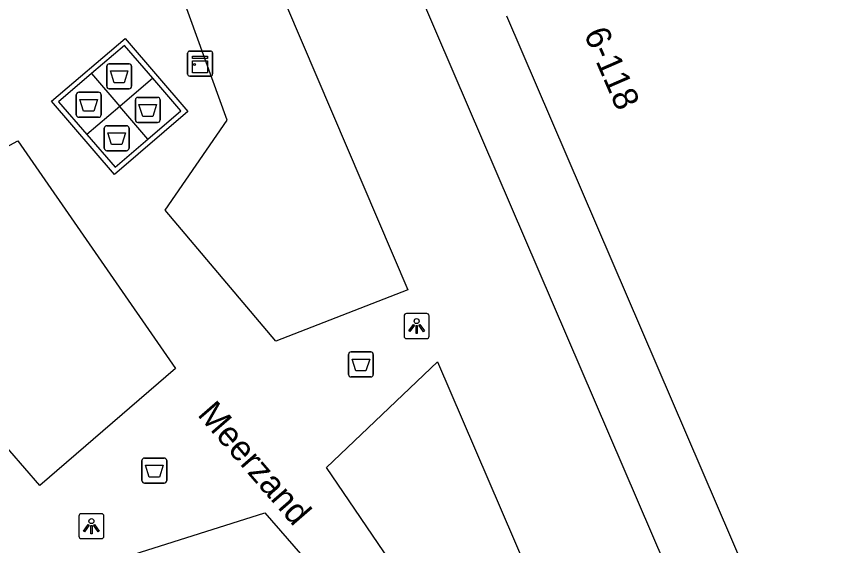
# Model space of a CAD drawing. Extents: x 155640 to 156810, y 382822 to 384046.
# Drawn here: x 156509.49 to 156542.78, y 383768.27 to 383789.39 of the extents above; entities that cross this region are included whole.
import ezdxf

# ---------------------------------------------------------------- set-up
doc = ezdxf.new("R2010")
doc.units = 0
for name, color, linetype in [('IMGEO_Afval_apart_plaats', 7, 'Continuous'), ('IMGEO_Afvalbak', 7, 'Continuous'), ('IMGEO_Kast', 7, 'Continuous'), ('IMGEO_Lichtpunt', 7, 'Continuous'), ('IMGEO_Lijnafwatering', 7, 'Continuous'), ('IMGEO_Muur', 7, 'Continuous'), ('IMGEO_Openbare_ruimte_label', 7, 'Continuous'), ('IMGEO_Pand', 7, 'Continuous'), ('IMGEO_Pand_nummerreeks', 7, 'Continuous'), ('IMGEO_Voetgangersgebied_open', 7, 'Continuous'), ('IMGEO_Voetpad_gesloten', 7, 'Continuous')]:
    doc.layers.add(name, color=color, linetype=linetype)

msp = doc.modelspace()

# ---------------------------------------------------------------- linework, layer by layer
at = {"layer": 'IMGEO_Afval_apart_plaats'}
for p, q in [((156513.093, 383786.609), (156513.093, 383787.409)), ((156513.093, 383787.409), (156513.093, 383786.609)), ((156513.193, 383787.509), (156513.983, 383787.509)), ((156513.983, 383787.509), (156513.193, 383787.509)), ((156514.083, 383787.409), (156514.083, 383786.609)), ((156514.083, 383786.609), (156514.083, 383787.409)), ((156511.874, 383785.473), (156511.874, 383786.273)), ((156511.874, 383786.273), (156511.874, 383785.473)), ((156511.974, 383786.373), (156512.764, 383786.373)), ((156512.764, 383786.373), (156511.974, 383786.373)), ((156512.864, 383786.273), (156512.864, 383785.473)), ((156512.864, 383785.473), (156512.864, 383786.273)), ((156513.983, 383786.509), (156513.193, 383786.509)), ((156513.193, 383786.509), (156513.983, 383786.509)), ((156514.235, 383785.264), (156514.235, 383786.064)), ((156514.235, 383786.064), (156514.235, 383785.264)), ((156514.335, 383786.164), (156515.125, 383786.164)), ((156515.125, 383786.164), (156514.335, 383786.164)), ((156515.225, 383786.064), (156515.225, 383785.264)), ((156515.225, 383785.264), (156515.225, 383786.064)), ((156512.764, 383785.373), (156511.974, 383785.373)), ((156511.974, 383785.373), (156512.764, 383785.373)), ((156512.993, 383784.136), (156512.993, 383784.936)), ((156512.993, 383784.936), (156512.993, 383784.136)), ((156513.093, 383785.036), (156513.883, 383785.036)), ((156513.883, 383785.036), (156513.093, 383785.036)), ((156513.983, 383784.936), (156513.983, 383784.136)), ((156513.983, 383784.136), (156513.983, 383784.936)), ((156515.125, 383785.164), (156514.335, 383785.164)), ((156514.335, 383785.164), (156515.125, 383785.164)), ((156513.883, 383784.036), (156513.093, 383784.036)), ((156513.093, 383784.036), (156513.883, 383784.036))]:
    msp.add_line(p, q, dxfattribs=at)
for points in [[(156513.236, 383787.223), (156513.94, 383787.223), (156513.791, 383786.753), (156513.385, 383786.753), (156513.236, 383787.223)], [(156512.017, 383786.087), (156512.721, 383786.087), (156512.572, 383785.617), (156512.166, 383785.617), (156512.017, 383786.087)], [(156514.378, 383785.878), (156515.082, 383785.878), (156514.933, 383785.408), (156514.527, 383785.408), (156514.378, 383785.878)], [(156513.136, 383784.75), (156513.84, 383784.75), (156513.691, 383784.28), (156513.285, 383784.28), (156513.136, 383784.75)]]:
    msp.add_lwpolyline(points, dxfattribs=at)
for centre, start, end in [((156513.193, 383787.409), 90, 180), ((156513.193, 383787.409), 90, 180), ((156513.983, 383787.409), 0, 90), ((156513.983, 383787.409), 360, 90), ((156513.193, 383786.609), 180, 270), ((156513.193, 383786.609), 180, 270), ((156513.983, 383786.609), 270, 0), ((156513.983, 383786.609), 270, 0), ((156511.974, 383786.273), 90, 180), ((156511.974, 383786.273), 90, 180), ((156512.764, 383786.273), 0, 90), ((156512.764, 383786.273), 360, 90), ((156514.335, 383786.064), 90, 180), ((156514.335, 383786.064), 90, 180), ((156515.125, 383786.064), 0, 90), ((156515.125, 383786.064), 360, 90), ((156511.974, 383785.473), 180, 270), ((156511.974, 383785.473), 180, 270), ((156512.764, 383785.473), 270, 0), ((156512.764, 383785.473), 270, 0), ((156514.335, 383785.264), 180, 270), ((156514.335, 383785.264), 180, 270), ((156515.125, 383785.264), 270, 0), ((156515.125, 383785.264), 270, 0), ((156513.093, 383784.936), 90, 180), ((156513.093, 383784.936), 90, 180), ((156513.883, 383784.936), 0, 90), ((156513.883, 383784.936), 360, 90), ((156513.093, 383784.136), 180, 270), ((156513.093, 383784.136), 180, 270), ((156513.883, 383784.136), 270, 0), ((156513.883, 383784.136), 270, 0)]:
    msp.add_arc(centre, 0.1, start, end, dxfattribs=at)
at = {"layer": 'IMGEO_Afvalbak'}
for p, q in [((156522.757, 383775.099), (156522.757, 383775.899)), ((156522.757, 383775.899), (156522.757, 383775.099)), ((156522.857, 383775.999), (156523.647, 383775.999)), ((156523.647, 383775.999), (156522.857, 383775.999)), ((156523.747, 383775.899), (156523.747, 383775.099)), ((156523.747, 383775.099), (156523.747, 383775.899)), ((156523.647, 383774.999), (156522.857, 383774.999)), ((156522.857, 383774.999), (156523.647, 383774.999)), ((156514.498, 383770.854), (156514.498, 383771.654)), ((156514.498, 383771.654), (156514.498, 383770.854)), ((156514.598, 383771.754), (156515.388, 383771.754)), ((156515.388, 383771.754), (156514.598, 383771.754)), ((156515.488, 383771.654), (156515.488, 383770.854)), ((156515.488, 383770.854), (156515.488, 383771.654)), ((156515.388, 383770.754), (156514.598, 383770.754)), ((156514.598, 383770.754), (156515.388, 383770.754))]:
    msp.add_line(p, q, dxfattribs=at)
for points in [[(156522.9, 383775.713), (156523.604, 383775.713), (156523.455, 383775.243), (156523.049, 383775.243), (156522.9, 383775.713)], [(156514.641, 383771.468), (156515.345, 383771.468), (156515.196, 383770.998), (156514.79, 383770.998), (156514.641, 383771.468)]]:
    msp.add_lwpolyline(points, dxfattribs=at)
for centre, start, end in [((156522.857, 383775.899), 90, 180), ((156522.857, 383775.899), 90, 180), ((156523.647, 383775.899), 0, 90), ((156523.647, 383775.899), 360, 90), ((156522.857, 383775.099), 180, 270), ((156522.857, 383775.099), 180, 270), ((156523.647, 383775.099), 270, 0), ((156523.647, 383775.099), 270, 0), ((156514.598, 383771.654), 90, 180), ((156514.598, 383771.654), 90, 180), ((156515.388, 383771.654), 0, 90), ((156515.388, 383771.654), 360, 90), ((156514.598, 383770.854), 180, 270), ((156514.598, 383770.854), 180, 270), ((156515.388, 383770.854), 270, 0), ((156515.388, 383770.854), 270, 0)]:
    msp.add_arc(centre, 0.1, start, end, dxfattribs=at)
at = {"layer": 'IMGEO_Kast'}
for p, q in [((156516.323, 383787.093), (156516.323, 383787.934)), ((156516.323, 383787.934), (156516.323, 383787.093)), ((156516.398, 383788.018), (156517.239, 383788.018)), ((156517.239, 383788.018), (156516.398, 383788.018)), ((156517.323, 383787.943), (156517.323, 383787.102)), ((156517.323, 383787.102), (156517.323, 383787.943)), ((156517.248, 383787.018), (156516.407, 383787.018)), ((156516.407, 383787.018), (156517.248, 383787.018))]:
    msp.add_line(p, q, dxfattribs=at)
for points in [[(156516.518, 383787.808), (156517.118, 383787.808), (156517.118, 383787.723), (156516.518, 383787.723), (156516.518, 383787.808)], [(156516.518, 383787.633), (156517.118, 383787.633), (156517.118, 383787.144), (156516.518, 383787.144), (156516.518, 383787.633)]]:
    msp.add_lwpolyline(points, dxfattribs=at)
msp.add_circle((156516.602, 383787.482), 0.0377, dxfattribs=at)
for centre, start, end in [((156516.401, 383787.94), 92.4484, 184.2845), ((156516.401, 383787.94), 92.4484, 184.2845), ((156517.245, 383787.94), 2.4484, 94.2845), ((156517.245, 383787.94), 2.4484, 94.2845), ((156516.401, 383787.096), 182.4484, 274.2845), ((156516.401, 383787.096), 182.4484, 274.2845), ((156517.245, 383787.096), 272.4484, 4.2845), ((156517.245, 383787.096), 272.4484, 4.2845)]:
    msp.add_arc(centre, 0.0779, start, end, dxfattribs=at)
at = {"layer": 'IMGEO_Lichtpunt'}
for p, q in [((156524.981, 383777.433), (156524.981, 383776.626)), ((156524.981, 383777.433), (156524.981, 383776.626)), ((156525.883, 383777.528), (156525.075, 383777.528)), ((156525.883, 383777.528), (156525.075, 383777.528)), ((156525.977, 383776.626), (156525.977, 383777.433)), ((156525.977, 383776.626), (156525.977, 383777.433)), ((156525.075, 383776.532), (156525.883, 383776.532)), ((156525.075, 383776.532), (156525.883, 383776.532)), ((156511.979, 383769.44), (156511.979, 383768.633)), ((156511.979, 383769.44), (156511.979, 383768.633)), ((156512.881, 383769.535), (156512.073, 383769.535)), ((156512.881, 383769.535), (156512.073, 383769.535)), ((156512.975, 383768.633), (156512.975, 383769.44)), ((156512.975, 383768.633), (156512.975, 383769.44)), ((156512.073, 383768.539), (156512.881, 383768.539)), ((156512.073, 383768.539), (156512.881, 383768.539))]:
    msp.add_line(p, q, dxfattribs=at)
for points in [[(156525.355, 383777.097), (156525.394, 383777.069), (156525.206, 383776.807), (156525.168, 383776.834), (156525.355, 383777.097)], [(156525.457, 383777.049), (156525.504, 383777.049), (156525.504, 383776.727), (156525.457, 383776.727), (156525.457, 383777.049)], [(156525.567, 383777.069), (156525.605, 383777.096), (156525.792, 383776.834), (156525.753, 383776.806), (156525.567, 383777.069)], [(156512.353, 383769.104), (156512.392, 383769.076), (156512.204, 383768.814), (156512.166, 383768.841), (156512.353, 383769.104)], [(156512.455, 383769.056), (156512.502, 383769.056), (156512.502, 383768.734), (156512.455, 383768.734), (156512.455, 383769.056)], [(156512.565, 383769.076), (156512.603, 383769.103), (156512.79, 383768.841), (156512.751, 383768.813), (156512.565, 383769.076)]]:
    msp.add_lwpolyline(points, dxfattribs=at)
for centre in [(156525.48, 383777.231), (156512.478, 383769.238)]:
    msp.add_circle(centre, 0.0994, dxfattribs=at)
for centre, start, end in [((156525.075, 383777.433), 90, 180), ((156525.075, 383777.433), 90, 180), ((156525.883, 383777.433), 0, 90), ((156525.883, 383777.433), 0, 90), ((156525.075, 383776.626), 180, 270), ((156525.075, 383776.626), 180, 270), ((156525.883, 383776.626), 270, 0), ((156525.883, 383776.626), 270, 360), ((156512.073, 383769.44), 90, 180), ((156512.073, 383769.44), 90, 180), ((156512.881, 383769.44), 0, 90), ((156512.881, 383769.44), 0, 90), ((156512.073, 383768.633), 180, 270), ((156512.073, 383768.633), 180, 270), ((156512.881, 383768.633), 270, 0), ((156512.881, 383768.633), 270, 360)]:
    msp.add_arc(centre, 0.0946, start, end, dxfattribs=at)
at = {"layer": 'IMGEO_Lijnafwatering'}
for points in [[(156526.985, 383787.107), (156519.088, 383805.472)], [(156534.883, 383768.741), (156526.985, 383787.107)], [(156542.78, 383750.376), (156534.883, 383768.741)]]:
    msp.add_lwpolyline(points, dxfattribs=at)
at = {"layer": 'IMGEO_Muur'}
for points in [[(156513.403, 383783.092), (156510.886, 383786.015), (156513.822, 383788.522), (156516.339, 383785.602), (156513.403, 383783.092)], [(156514.929, 383786.932), (156513.801, 383788.241), (156512.485, 383787.117)], [(156512.485, 383787.117), (156511.168, 383785.994), (156512.296, 383784.684)], [(156514.74, 383784.499), (156516.056, 383785.624), (156514.929, 383786.932)], [(156512.296, 383784.684), (156513.425, 383783.374), (156514.74, 383784.499)]]:
    msp.add_lwpolyline(points, dxfattribs=at)
at = {"layer": 'IMGEO_Pand'}
msp.add_lwpolyline([(156538.691, 383767.078), (156529.087, 383789.41)], dxfattribs=at)
at = {"layer": 'IMGEO_Voetgangersgebied_open'}
for points in [[(156519.85, 383776.428), (156515.42, 383781.667), (156517.905, 383785.259), (156516.126, 383790.192), (156519.07, 383792.672), (156525.122, 383778.477), (156519.85, 383776.428)], [(156515.843, 383775.339), (156510.412, 383770.654), (156502.001, 383780.354), (156509.534, 383784.434), (156515.843, 383775.339)], [(156527.144, 383763.648), (156521.87, 383771.375), (156526.321, 383775.6), (156530.378, 383766.154), (156527.144, 383763.648)], [(156520.512, 383759.022), (156513.128, 383767.581), (156519.416, 383769.575), (156525.131, 383762.997), (156520.512, 383759.022)]]:
    msp.add_lwpolyline(points, dxfattribs=at)
at = {"layer": 'IMGEO_Voetpad_gesloten'}
for points in [[(156512.485, 383787.117), (156513.613, 383785.808)], [(156514.929, 383786.932), (156513.613, 383785.808)], [(156513.613, 383785.808), (156512.296, 383784.684)], [(156514.74, 383784.499), (156513.613, 383785.808)]]:
    msp.add_lwpolyline(points, dxfattribs=at)

# ---------------------------------------------------------------- texts
at = {"layer": 'IMGEO_Openbare_ruimte_label'}
msp.add_text('Meerzand', height=1, rotation=310.9433, dxfattribs=at).set_placement((156516.684, 383773.481))
at = {"layer": 'IMGEO_Pand_nummerreeks'}
msp.add_text('6-118', height=1, rotation=293.5025, dxfattribs=at).set_placement((156532.152, 383788.711))

doc.saveas('drawing.dxf')
